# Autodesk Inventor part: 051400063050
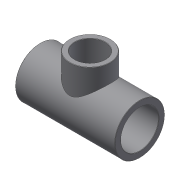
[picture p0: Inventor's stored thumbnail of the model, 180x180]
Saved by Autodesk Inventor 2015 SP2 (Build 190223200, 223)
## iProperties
Created: 2017-10
Part Number: 051400063050
Material: Generic
Description: PLASSON REDUCER TEE - CEMENT PVC 63-50-63
Document SubType Name: Modeling
Designer: KIM
Density: 1 g/cm^3
Appearance: Default
Author: KIM
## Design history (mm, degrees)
derived "051400.ipt"
feature "Solid1::051400.ipt"
feature "Solid2::051400.ipt"
tag "TaggingFeature1"
body "Solid1"
other parameters: "d0" = 144, "d1" = 77, "d2" = 38, "d4" = 63, "d5" = 56.7, "d7" = 0.63, "d8" = 38, "d9" = 65.5, "d10" = 61, "d12" = 45, "d23" = 31, "d24" = 0.63, "d26" = 0, "d30" = 0, "d32" = 0, "d_" = 63, "E_" = 77, "H_" = 144, "l_" = 38, "Z_" = 14, "E_1" = 61, "l_1" = 31, "Z_1" = 12.5, "H_1" = 104
